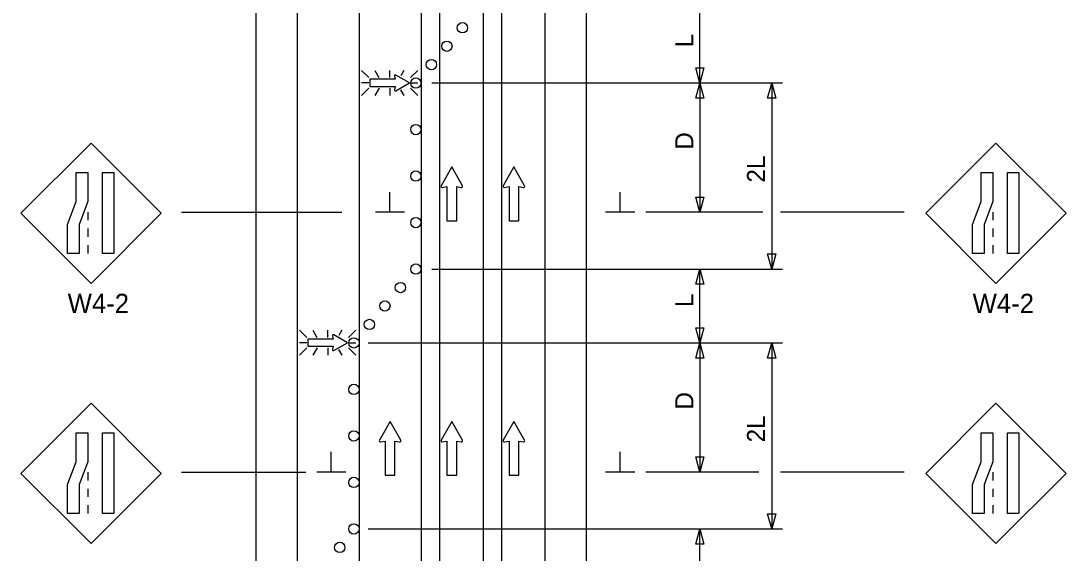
# Model space of a CAD drawing. Extents: x 16383 to 18481, y 5609 to 7023.
# Drawn here: x 16767.7 to 17172.5, y 6526.2 to 6732.2 of the extents above; entities that cross this region are included whole.
import ezdxf

# ---------------------------------------------------------------- set-up
doc = ezdxf.new("R2010")
doc.units = 0
for name, color, linetype in [('ALI_LEGAL_EX', 7, 'Continuous'), ('MT_SCRATCH_LEVEL_E', 7, 'Continuous'), ('PAVT_EDGE_EX', 7, 'Continuous'), ('TRAFFIC_SIGNS_PR', 7, 'Continuous'), ('TYPICAL_TEXT_DIMEN_PR', 7, 'Continuous')]:
    doc.layers.add(name, color=color, linetype=linetype)

msp = doc.modelspace()

# ---------------------------------------------------------------- linework, layer by layer
at = {"layer": 'ALI_LEGAL_EX'}
for p, q in [((16898.69, 7022.86), (16898.69, 6323.13)), ((16922.69, 7022.86), (16922.69, 6323.13)), ((16946.69, 7022.86), (16946.69, 6323.13)), ((16929.88, 7005.57), (16929.88, 6176.39)), ((16953.88, 7005.57), (16953.88, 6176.39)), ((16953.88, 7005.57), (16953.88, 6176.39))]:
    msp.add_line(p, q, dxfattribs=at)
for points in [[(16898.69, 6682.86), (16898.69, 6657.86)], [(16922.69, 6682.86), (16922.69, 6657.86)], [(16946.69, 6682.86), (16946.69, 6657.86)], [(16898.69, 6582.86), (16898.69, 6557.86)], [(16922.69, 6582.86), (16922.69, 6557.86)], [(16946.69, 6582.86), (16946.69, 6557.86)]]:
    msp.add_lwpolyline(points, dxfattribs=at)
at = {"layer": 'MT_SCRATCH_LEVEL_E'}
for p, q in [((16934.6, 6675.63), (16930.49, 6668.39)), ((16938.74, 6668.39), (16934.6, 6675.63)), ((16958.65, 6675.63), (16954.54, 6668.39)), ((16962.8, 6668.39), (16958.65, 6675.63)), ((16930.97, 6667.71), (16932.74, 6668.02)), ((16932.74, 6668.02), (16932.74, 6654.77)), ((16936.49, 6654.77), (16936.49, 6668.02)), ((16936.49, 6668.02), (16938.26, 6667.71)), ((16955.02, 6667.71), (16956.8, 6668.02)), ((16956.8, 6668.02), (16956.8, 6654.77)), ((16960.54, 6654.77), (16960.54, 6668.02)), ((16960.54, 6668.02), (16962.32, 6667.71)), ((16932.74, 6654.77), (16936.49, 6654.77)), ((16956.8, 6654.77), (16960.54, 6654.77)), ((16910.69, 6577.17), (16906.58, 6569.93)), ((16914.84, 6569.93), (16910.69, 6577.17)), ((16934.6, 6577.17), (16930.49, 6569.93)), ((16938.74, 6569.93), (16934.6, 6577.17)), ((16958.65, 6577.17), (16954.54, 6569.93)), ((16962.8, 6569.93), (16958.65, 6577.17)), ((16907.06, 6569.24), (16908.84, 6569.56)), ((16908.84, 6569.56), (16908.84, 6556.3)), ((16912.58, 6556.3), (16912.58, 6569.56)), ((16912.58, 6569.56), (16914.36, 6569.24)), ((16930.97, 6569.24), (16932.74, 6569.56)), ((16932.74, 6569.56), (16932.74, 6556.3)), ((16936.49, 6556.3), (16936.49, 6569.56)), ((16936.49, 6569.56), (16938.26, 6569.24)), ((16955.02, 6569.24), (16956.8, 6569.56)), ((16956.8, 6569.56), (16956.8, 6556.3)), ((16960.54, 6556.3), (16960.54, 6569.56)), ((16960.54, 6569.56), (16962.32, 6569.24)), ((16908.84, 6556.3), (16912.58, 6556.3)), ((16932.74, 6556.3), (16936.49, 6556.3)), ((16956.8, 6556.3), (16960.54, 6556.3))]:
    msp.add_line(p, q, dxfattribs=at)
for centre, start, end in [((16930.89, 6668.17), 150.4248, 279.9638), ((16938.33, 6668.17), 260.0362, 29.7731), ((16954.95, 6668.17), 150.4248, 279.9638), ((16962.39, 6668.17), 260.0362, 29.7731), ((16906.99, 6569.7), 150.4248, 279.9638), ((16914.43, 6569.7), 260.0362, 29.7731), ((16930.89, 6569.7), 150.4248, 279.9638), ((16938.33, 6569.7), 260.0362, 29.7731), ((16954.95, 6569.7), 150.4248, 279.9638), ((16962.39, 6569.7), 260.0362, 29.7731)]:
    msp.add_arc(centre, 0.463, start, end, dxfattribs=at)
at = {"layer": 'PAVT_EDGE_EX'}
for p, q in [((16858.69, 6927.61), (16858.69, 6052.61)), ((16874.69, 6927.61), (16874.69, 6052.61)), ((16970.69, 6927.61), (16970.69, 6052.61)), ((16986.69, 6927.61), (16986.69, 6052.61))]:
    msp.add_line(p, q, dxfattribs=at)
at = {"layer": 'TRAFFIC_SIGNS_PR'}
for p, q in [((16902.47, 6710.21), (16899.65, 6713.03)), ((16904.77, 6713.03), (16906.39, 6710.21)), ((16910.55, 6710.21), (16910.55, 6713.03)), ((16916.02, 6713.03), (16914.82, 6710.94)), ((16921.46, 6713.03), (16918.64, 6710.21)), ((16902.47, 6708.18), (16899.65, 6708.18)), ((16918.64, 6708.18), (16921.46, 6708.18)), ((16902.47, 6706.15), (16899.65, 6703.32)), ((16906.42, 6706.15), (16904.79, 6703.33)), ((16910.55, 6706.15), (16910.55, 6703.33)), ((16914.74, 6705.51), (16916, 6703.33)), ((16921.46, 6703.33), (16918.64, 6706.15)), ((16794.87, 6684.86), (16767.71, 6657.71)), ((16822.02, 6657.71), (16794.87, 6684.86)), ((17145.36, 6684.86), (17118.21, 6657.71)), ((17172.52, 6657.71), (17145.36, 6684.86)), ((16767.71, 6657.71), (16794.87, 6630.56)), ((16793.62, 6658.2), (16793.62, 6655)), ((16794.87, 6630.56), (16822.02, 6657.71)), ((17118.21, 6657.71), (17145.36, 6630.56)), ((17144.12, 6658.2), (17144.12, 6655)), ((17145.36, 6630.56), (17172.52, 6657.71)), ((16793.62, 6651.8), (16793.62, 6648.6)), ((17144.12, 6651.8), (17144.12, 6648.6)), ((16793.62, 6645.4), (16793.62, 6642.2)), ((17144.12, 6645.4), (17144.12, 6642.2)), ((16878.47, 6609.65), (16875.65, 6612.47)), ((16880.77, 6612.47), (16882.39, 6609.65)), ((16886.55, 6609.65), (16886.55, 6612.47)), ((16892.02, 6612.47), (16890.82, 6610.37)), ((16897.46, 6612.47), (16894.64, 6609.65)), ((16878.47, 6607.61), (16875.65, 6607.61)), ((16894.64, 6607.61), (16897.46, 6607.61)), ((16878.47, 6605.58), (16875.65, 6602.76)), ((16882.42, 6605.58), (16880.79, 6602.76)), ((16886.55, 6605.58), (16886.55, 6602.76)), ((16890.74, 6604.95), (16892, 6602.76)), ((16897.46, 6602.77), (16894.64, 6605.58)), ((16794.87, 6584.16), (16767.71, 6557.01)), ((16822.02, 6557.01), (16794.87, 6584.16)), ((17145.36, 6584.16), (17118.21, 6557.01)), ((17172.52, 6557.01), (17145.36, 6584.16)), ((16767.71, 6557.01), (16794.87, 6529.86)), ((16793.62, 6557.5), (16793.62, 6554.3)), ((16794.87, 6529.86), (16822.02, 6557.01)), ((17118.21, 6557.01), (17145.36, 6529.86)), ((17144.12, 6557.5), (17144.12, 6554.3)), ((17145.36, 6529.86), (17172.52, 6557.01)), ((16793.62, 6551.1), (16793.62, 6547.9)), ((17144.12, 6551.1), (17144.12, 6547.9)), ((16793.62, 6544.7), (16793.62, 6541.5)), ((17144.12, 6544.7), (17144.12, 6541.5))]:
    msp.add_line(p, q, dxfattribs=at)
for points in [[(16912.38, 6710.86), (16912.61, 6709.56), (16902.89, 6709.56), (16902.89, 6706.82), (16912.61, 6706.82), (16912.38, 6705.52)], [(16912.88, 6705.16), (16918.19, 6708.18), (16912.88, 6711.22)], [(16888.88, 6604.6), (16894.19, 6607.61), (16888.88, 6610.66)], [(16888.38, 6610.3), (16888.61, 6609), (16878.89, 6609), (16878.89, 6606.26), (16888.61, 6606.26), (16888.38, 6604.95)]]:
    msp.add_lwpolyline(points, dxfattribs=at)
for points in [[(16793.62, 6673.45), (16793.62, 6662.26), (16790.28, 6653.38), (16790.28, 6642.2), (16785.78, 6642.2), (16785.78, 6653.38), (16789.13, 6662.26), (16789.13, 6673.45)], [(16803.76, 6673.45), (16803.76, 6642.2), (16799.26, 6642.2), (16799.26, 6673.45)], [(17144.12, 6673.45), (17144.12, 6662.26), (17140.77, 6653.38), (17140.77, 6642.2), (17136.28, 6642.2), (17136.28, 6653.38), (17139.62, 6662.26), (17139.62, 6673.45)], [(17154.25, 6673.45), (17154.25, 6642.2), (17149.76, 6642.2), (17149.76, 6673.45)], [(16793.62, 6572.75), (16793.62, 6561.56), (16790.28, 6552.68), (16790.28, 6541.5), (16785.78, 6541.5), (16785.78, 6552.68), (16789.13, 6561.56), (16789.13, 6572.75)], [(16803.76, 6572.75), (16803.76, 6541.5), (16799.26, 6541.5), (16799.26, 6572.75)], [(17144.12, 6572.75), (17144.12, 6561.56), (17140.77, 6552.68), (17140.77, 6541.5), (17136.28, 6541.5), (17136.28, 6552.68), (17139.62, 6561.56), (17139.62, 6572.75)], [(17154.25, 6572.75), (17154.25, 6541.5), (17149.76, 6541.5), (17149.76, 6572.75)]]:
    msp.add_lwpolyline(points, close=True, dxfattribs=at)
for centre in [(16938.69, 6729.53), (16932.69, 6722.39), (16926.69, 6715.25), (16920.69, 6708.11), (16920.69, 6690.11), (16920.69, 6672.11), (16920.69, 6654.11), (16920.69, 6636.11), (16914.69, 6628.97), (16908.69, 6621.83), (16902.69, 6614.69), (16896.69, 6607.55), (16896.69, 6589.54), (16896.69, 6571.54), (16896.69, 6553.54), (16896.69, 6535.54), (16891.2, 6528.41)]:
    msp.add_circle(centre, 2, dxfattribs=at)
for centre, start, end in [((16912.72, 6710.92), 61.4833, 189.9593), ((16912.72, 6705.46), 170.7308, 298.8916), ((16888.72, 6610.36), 61.4833, 189.9593), ((16888.72, 6604.9), 170.7308, 298.8916)]:
    msp.add_arc(centre, 0.341, start, end, dxfattribs=at)
at = {"layer": 'TYPICAL_TEXT_DIMEN_PR'}
for p, q in [((17030.69, 6708.11), (17030.69, 6738.67)), ((17030.69, 6708.11), (17029.12, 6713.97)), ((17029.12, 6713.97), (17030.69, 6713.97)), ((17030.69, 6713.97), (17032.26, 6713.97)), ((17032.26, 6713.97), (17030.69, 6708.11)), ((17062.74, 6708.11), (16926.92, 6708.11)), ((17029.12, 6702.24), (17030.69, 6708.11)), ((17030.69, 6708.11), (17030.69, 6658.11)), ((17030.69, 6708.11), (17032.26, 6702.24)), ((17056.93, 6702.24), (17058.5, 6708.11)), ((17058.5, 6708.11), (17060.07, 6702.24)), ((17058.5, 6708.11), (17058.5, 6636.11)), ((17030.69, 6702.24), (17029.12, 6702.24)), ((17032.26, 6702.24), (17030.69, 6702.24)), ((17058.5, 6702.24), (17056.93, 6702.24)), ((17060.07, 6702.24), (17058.5, 6702.24)), ((16910.64, 6658.11), (16910.64, 6665.89)), ((16999.82, 6658.11), (16999.82, 6665.89)), ((17030.69, 6658.11), (17029.12, 6663.97)), ((17029.12, 6663.97), (17030.69, 6663.97)), ((17030.69, 6663.97), (17032.26, 6663.97)), ((17032.26, 6663.97), (17030.69, 6658.11)), ((17058.5, 6662.98), (17058.5, 6659.21)), ((16829.94, 6658.11), (16891.95, 6658.11)), ((16916.26, 6658.11), (16905.01, 6658.11)), ((17005.44, 6658.11), (16994.19, 6658.11)), ((17055.04, 6658.11), (17009.69, 6658.11)), ((17109.74, 6658.11), (17061.87, 6658.11)), ((17058.5, 6636.11), (17056.93, 6641.97)), ((17056.93, 6641.97), (17058.5, 6641.97)), ((17058.5, 6641.97), (17060.07, 6641.97)), ((17060.07, 6641.97), (17058.5, 6636.11)), ((16926.92, 6636.11), (17062.74, 6636.11)), ((17029.12, 6630.24), (17030.69, 6636.11)), ((17030.69, 6607.55), (17030.69, 6636.11)), ((17030.69, 6636.11), (17032.26, 6630.24)), ((17030.69, 6630.24), (17029.12, 6630.24)), ((17032.26, 6630.24), (17030.69, 6630.24)), ((17030.69, 6607.55), (17029.12, 6613.41)), ((17029.12, 6613.41), (17030.69, 6613.41)), ((17030.69, 6613.41), (17032.26, 6613.41)), ((17032.26, 6613.41), (17030.69, 6607.55)), ((16902.24, 6607.55), (17062.74, 6607.55)), ((17029.12, 6601.68), (17030.69, 6607.55)), ((17030.69, 6607.55), (17030.69, 6557.55)), ((17030.69, 6607.55), (17032.26, 6601.68)), ((17056.93, 6601.68), (17058.5, 6607.55)), ((17058.5, 6607.55), (17060.07, 6601.68)), ((17058.5, 6607.55), (17058.5, 6535.55)), ((17030.69, 6601.68), (17029.12, 6601.68)), ((17032.26, 6601.68), (17030.69, 6601.68)), ((17058.5, 6601.68), (17056.93, 6601.68)), ((17060.07, 6601.68), (17058.5, 6601.68)), ((16887.91, 6557.55), (16887.91, 6565.33)), ((16999.82, 6557.55), (16999.82, 6565.33)), ((17030.69, 6557.55), (17029.12, 6563.41)), ((17029.12, 6563.41), (17030.69, 6563.41)), ((17030.69, 6563.41), (17032.26, 6563.41)), ((17032.26, 6563.41), (17030.69, 6557.55)), ((17058.5, 6562.41), (17058.5, 6558.65)), ((16829.94, 6557.55), (16878.12, 6557.55)), ((16893.53, 6557.55), (16882.28, 6557.55)), ((17005.44, 6557.55), (16994.19, 6557.55)), ((17053.49, 6557.55), (17009.69, 6557.55)), ((17109.74, 6557.55), (17061.87, 6557.55)), ((17058.5, 6535.55), (17056.93, 6541.41)), ((17056.93, 6541.41), (17058.5, 6541.41)), ((17058.5, 6541.41), (17060.07, 6541.41)), ((17060.07, 6541.41), (17058.5, 6535.55)), ((16902.24, 6535.54), (17062.74, 6535.54)), ((17029.12, 6529.68), (17030.69, 6535.54)), ((17030.69, 6504.98), (17030.69, 6535.54)), ((17030.69, 6535.54), (17032.26, 6529.68)), ((17030.69, 6529.68), (17029.12, 6529.68)), ((17032.26, 6529.68), (17030.69, 6529.68))]:
    msp.add_line(p, q, dxfattribs=at)

# ---------------------------------------------------------------- texts
at = {"layer": 'TRAFFIC_SIGNS_PR'}
for p in [(16785.83, 6619.12), (17136.32, 6619.12)]:
    msp.add_text('W4-2', height=7.44, dxfattribs=at).set_placement(p)
at = {"layer": 'TYPICAL_TEXT_DIMEN_PR'}
for s, p in [('L', (17028.14, 6721.96)), ('D', (17028.14, 6682.33)), ('2L', (17055.94, 6669.61)), ('L', (17028.14, 6621.4)), ('D', (17028.14, 6581.76)), ('2L', (17055.94, 6569.05))]:
    msp.add_text(s, height=7, rotation=90, dxfattribs=at).set_placement(p)

doc.saveas('drawing.dxf')
